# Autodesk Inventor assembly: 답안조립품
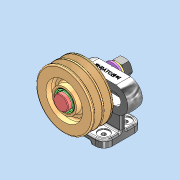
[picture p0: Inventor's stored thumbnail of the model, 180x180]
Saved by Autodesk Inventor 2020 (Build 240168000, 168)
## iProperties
Created: 2025-01
Part Number: 답안조립품
Document SubType Name: Assembly
Designer: 1강의실14
Author: 1강의실14
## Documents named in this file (9)
- C:\Users\1강의실14\Desktop\750103V1001\답안조립품.iam
- C:\Users\1강의실14\Desktop\750103V1001\본체.ipt
- C:\Users\1강의실14\Desktop\750103V1001\축.ipt
- C:\Users\1강의실14\Desktop\750103V1001\평 와셔 M16.ipt
- C:\Users\1강의실14\Desktop\750103V1001\스프링 와셔 M16.ipt
- C:\Users\1강의실14\Desktop\750103V1001\육각 너트 M16.ipt
- C:\Users\1강의실14\Desktop\750103V1001\V-벨트 풀리.ipt
- C:\Users\1강의실14\Desktop\750103V1001\육각 머리 볼트 M8x80.ipt
- C:\Users\1강의실14\Desktop\750103V1001\깊은 홈 볼 베어링 6804.ipt
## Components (1 placed, 1 different names)
1. V-벨트 풀리:1
